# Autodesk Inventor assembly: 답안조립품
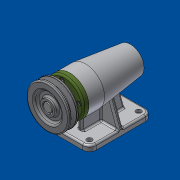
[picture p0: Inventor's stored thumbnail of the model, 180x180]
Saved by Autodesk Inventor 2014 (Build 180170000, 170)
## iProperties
Created: 2018-09
Part Number: 답안조립품
Document SubType Name: Assembly
Designer: 702-20
Author: 702-20
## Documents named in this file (12)
- C:\Users\702-20\Desktop\480908V1002\답안조립품.iam
- C:\Users\702-20\Desktop\480908V1002\본체.ipt
- C:\Users\702-20\Desktop\480908V1002\V벨트풀리.ipt
- C:\Users\702-20\Desktop\480908V1002\멈춤나사 M3.ipt
- C:\Users\702-20\Desktop\480908V1002\베어링 6004.ipt
- C:\Users\702-20\Desktop\480908V1002\베어링 51202.ipt
- C:\Users\702-20\Desktop\480908V1002\볼트 M4.ipt
- C:\Users\702-20\Desktop\480908V1002\어댑터슬리브.ipt
- C:\Users\702-20\Desktop\480908V1002\오일 실.ipt
- C:\Users\702-20\Desktop\480908V1002\축.ipt
- C:\Users\702-20\Desktop\480908V1002\커버.ipt
- C:\Users\702-20\Desktop\480908V1002\키 5 x 5 x 16.ipt
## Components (1 placed, 1 different names)
1. V벨트풀리:1 — 각도:1, 플러쉬:2
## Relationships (2: Angle 1, Flush 1)
- 각도:1 [Angle]: V벨트풀리:1
- 플러쉬:2 [Flush]: V벨트풀리:1
